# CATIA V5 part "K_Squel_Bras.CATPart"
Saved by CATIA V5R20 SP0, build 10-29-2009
Part number: Squelette_bras
Publications: "Point.2", "Plan.4", "Plan.1"
Bounding box of the stored display mesh (mm): x -159 to -87, y -106.066 to -66.066, z 106.066 to 106.066
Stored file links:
  G:\Khaled_CFAO_2011\ST2M\ST2M_GR2\plakomicki\Khaled\CAD_ThinkMOTION\K_Squel_Bras.CATPart
  G:\Khaled_CFAO_2011\ST2M\ST2M_GR2\plakomicki\Khaled\CAD_ThinkMOTION\K_Squelette.CATProduct
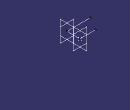
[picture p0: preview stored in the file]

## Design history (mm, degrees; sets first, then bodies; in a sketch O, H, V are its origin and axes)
Set1
  Plane1: linked copy from another document
  Point1: linked copy from another document
Set2
  Plane2 "Plan_ref_bras": type OffsetPt, RefPlane Plane1, RefPoint Point1
  Line1 "axe_pivot_bras_struct": type PtDir, RefPoint Point1, Direction Plane2, Start 0, End -72
  Plane3: type OffsetPt, RefPlane zx-plane, RefPoint Point1
  Plane4: type Offset, RefPlane Plane3, Offset 40
  Point2: type OnPlane, Support Plane4, RefPoint Point1, H 0, V 0, Direction (-1, 0, 0)
  Line2 "longueur_bras": type PtPt, FirstPoint Point1, SecondPoint Point2
  Line3 "axe_pivot_bras_amortisseur": type PtDir, RefPoint Point2, Direction Plane2, Start 0, End -48
  Plane5: type OffsetPt, RefPlane Plane2, RefPoint Point2
Body1 (main body)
